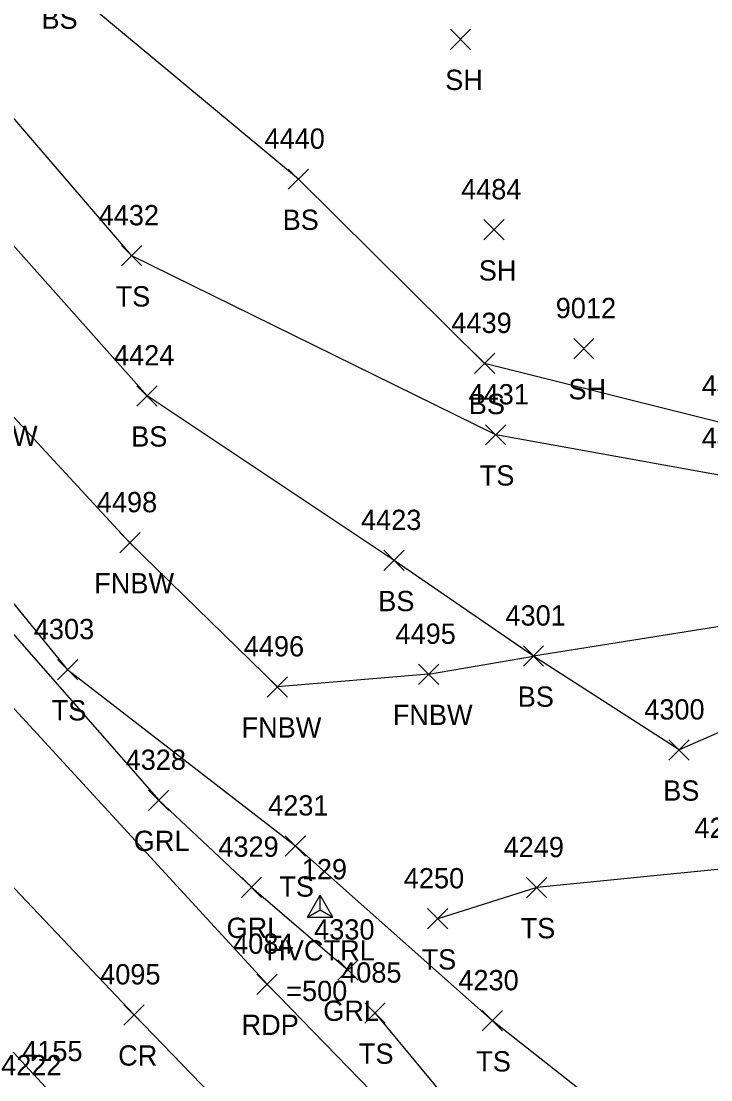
# Model space of a CAD drawing. Extents: x 1482574 to 1485769, y 580696 to 595649.
# Drawn here: x 1483633.6 to 1483701.6, y 583487.9 to 583592.2 of the extents above; entities that cross this region are included whole.
import ezdxf

# ---------------------------------------------------------------- set-up
doc = ezdxf.new("R2010")
doc.units = 0
for name, color, linetype in [('C_A', 7, 'Continuous'), ('C_C', 7, 'Continuous'), ('C_I', 7, 'Continuous'), ('CPSM', 7, 'Continuous'), ('L_A', 7, 'Continuous'), ('L_I', 7, 'Continuous'), ('L_TIC', 7, 'Continuous'), ('LELB', 7, 'Continuous'), ('LFNC', 7, 'Continuous'), ('P_A', 7, 'Continuous'), ('P_I', 7, 'Continuous'), ('P_TIC', 7, 'Continuous'), ('PET', 7, 'Continuous'), ('PRC', 7, 'Continuous'), ('R_A', 7, 'Continuous'), ('R_I', 7, 'Continuous'), ('R_TIC', 7, 'Continuous'), ('RGR', 7, 'Continuous')]:
    doc.layers.add(name, color=color, linetype=linetype)

msp = doc.modelspace()

# ---------------------------------------------------------------- linework, layer by layer
at = {"layer": 'CPSM'}
for p, q in [((1483661.81, 583503.91), (1483663.06, 583506.07)), ((1483664.31, 583503.91), (1483663.06, 583506.07)), ((1483663.06, 583504.63), (1483663.06, 583506.07)), ((1483661.81, 583503.91), (1483663.06, 583504.63)), ((1483663.06, 583504.63), (1483663.06, 583504.63)), ((1483663.06, 583504.63), (1483664.31, 583503.91)), ((1483661.81, 583503.91), (1483664.31, 583503.91))]:
    msp.add_line(p, q, dxfattribs=at)
at = {"layer": 'L_TIC'}
for points in [[(1483675.91, 583589.43), (1483677.91, 583591.43)], [(1483677.91, 583589.43), (1483675.91, 583591.43)], [(1483659.93, 583575.64), (1483661.93, 583577.64)], [(1483661.93, 583575.64), (1483659.93, 583577.64)], [(1483679.22, 583570.65), (1483681.22, 583572.65)], [(1483681.22, 583570.65), (1483679.22, 583572.65)], [(1483643.49, 583568.1), (1483645.49, 583570.09)], [(1483645.49, 583568.1), (1483643.49, 583570.09)], [(1483688.07, 583558.94), (1483690.07, 583560.94)], [(1483690.07, 583558.94), (1483688.07, 583560.94)], [(1483678.28, 583557.48), (1483680.28, 583559.48)], [(1483680.28, 583557.48), (1483678.28, 583559.48)], [(1483645, 583554.28), (1483647, 583556.28)], [(1483647, 583554.28), (1483645, 583556.28)], [(1483679.39, 583550.44), (1483681.39, 583552.44)], [(1483681.39, 583550.44), (1483679.39, 583552.44)], [(1483643.31, 583539.81), (1483645.31, 583541.8)], [(1483645.31, 583539.81), (1483643.31, 583541.8)], [(1483669.36, 583538.06), (1483671.36, 583540.06)], [(1483671.36, 583538.06), (1483669.36, 583540.06)], [(1483683.11, 583528.64), (1483685.11, 583530.64)], [(1483685.11, 583528.64), (1483683.11, 583530.64)], [(1483637.18, 583527.3), (1483639.18, 583529.29)], [(1483639.18, 583527.3), (1483637.18, 583529.29)], [(1483672.76, 583526.84), (1483674.76, 583528.84)], [(1483674.76, 583526.84), (1483672.76, 583528.84)], [(1483657.85, 583525.6), (1483659.85, 583527.6)], [(1483659.85, 583525.6), (1483657.85, 583527.6)], [(1483697.46, 583519.38), (1483699.46, 583521.38)], [(1483699.46, 583519.38), (1483697.46, 583521.38)], [(1483659.63, 583509.92), (1483661.63, 583511.92)], [(1483661.63, 583509.92), (1483659.63, 583511.92)], [(1483683.43, 583505.82), (1483685.43, 583507.82)], [(1483685.43, 583505.82), (1483683.43, 583507.82)], [(1483673.66, 583502.74), (1483675.66, 583504.74)], [(1483675.66, 583502.74), (1483673.66, 583504.74)], [(1483667.48, 583493.45), (1483669.48, 583495.45)], [(1483669.48, 583493.45), (1483667.48, 583495.45)], [(1483679.05, 583492.7), (1483681.05, 583494.69)], [(1483681.05, 583492.7), (1483679.05, 583494.69)]]:
    msp.add_lwpolyline(points, dxfattribs=at)
at = {"layer": 'LELB'}
for points in [[(1483742.4, 583552.69), (1483725.76, 583549.56), (1483703.96, 583552.3), (1483679.28, 583558.48), (1483660.93, 583576.64), (1483637.15, 583596.46), (1483615.07, 583609.81), (1483602.78, 583616.94), (1483607.94, 583643.09), (1483616.8, 583658.52), (1483628.11, 583655.29), (1483633.82, 583672.03), (1483624.29, 583682.77), (1483626.37, 583696.2), (1483621.21, 583717.98), (1483597.21, 583736.66), (1483595.87, 583748.89), (1483596.51, 583775.53), (1483606.42, 583791.46), (1483628.46, 583809.01), (1483643.23, 583813.61)], [(1483638.18, 583528.29), (1483623.83, 583545.9), (1483615.16, 583563.63), (1483598.18, 583580.85), (1483584.91, 583606.41), (1483576.29, 583635.39), (1483571.8, 583664.7), (1483567.86, 583692.01), (1483571.37, 583722.39), (1483575.73, 583749.31), (1483582.05, 583780.14), (1483587.02, 583800.96), (1483586.5, 583812.63)], [(1483741.79, 583540.7), (1483726.53, 583544.33), (1483704.06, 583547.16), (1483680.39, 583551.44), (1483644.49, 583569.09), (1483629.94, 583586.02), (1483612.61, 583602.16), (1483600.95, 583609.44)], [(1483735.81, 583533.58), (1483716.93, 583528.46), (1483698.46, 583520.38), (1483684.11, 583529.64), (1483670.36, 583539.06), (1483646, 583555.28), (1483615.51, 583589.53), (1483606.5, 583601.33)], [(1483638.18, 583528.29), (1483660.63, 583510.92)], [(1483766.23, 583459.85), (1483754.62, 583477), (1483742.54, 583496.59), (1483736.27, 583517.77), (1483716.64, 583511.25), (1483703.24, 583508.71), (1483684.43, 583506.82), (1483674.66, 583503.74)], [(1483809.69, 583356.53), (1483787.72, 583374.89), (1483761.98, 583401.74), (1483738.15, 583426.92), (1483736.24, 583442.93), (1483724.82, 583459.78), (1483706.28, 583473.02), (1483680.05, 583493.69), (1483660.63, 583510.92)], [(1483668.48, 583494.45), (1483691.51, 583466.71), (1483717.71, 583441.81), (1483741.58, 583415.89), (1483765.61, 583390.35), (1483787.36, 583370.39)]]:
    msp.add_lwpolyline(points, dxfattribs=at)
at = {"layer": 'LFNC'}
for points in [[(1483673.76, 583527.84), (1483658.85, 583526.6), (1483644.31, 583540.81), (1483630.87, 583555.33)], [(1483705.13, 583532.97), (1483684.11, 583529.64)], [(1483673.76, 583527.84), (1483684.11, 583529.64)]]:
    msp.add_lwpolyline(points, dxfattribs=at)
at = {"layer": 'P_TIC'}
for points in [[(1483656.83, 583496.29), (1483658.83, 583498.29)], [(1483658.83, 583496.29), (1483656.83, 583498.29)], [(1483643.72, 583493.27), (1483645.72, 583495.27)], [(1483645.72, 583493.27), (1483643.72, 583495.27)]]:
    msp.add_lwpolyline(points, dxfattribs=at)
at = {"layer": 'PET'}
for points in [[(1483734.47, 583384.83), (1483710.77, 583410.08), (1483685.69, 583436.09), (1483659.83, 583462.34), (1483636.38, 583486.71), (1483612.84, 583512.18), (1483585.95, 583538.63), (1483563.03, 583563.69), (1483555.97, 583565.92)], [(1483628.83, 583528.85), (1483657.83, 583497.29)], [(1483757.87, 583394.57), (1483732.77, 583420.47), (1483707.3, 583446.44), (1483681.81, 583472.64), (1483657.83, 583497.29)]]:
    msp.add_lwpolyline(points, dxfattribs=at)
at = {"layer": 'PRC'}
for points in [[(1483618.73, 583521.67), (1483644.72, 583494.27)], [(1484022.3, 583100.04), (1483990.86, 583133.2), (1483962.86, 583162.55), (1483929.32, 583197.8), (1483898.21, 583230.47), (1483864.91, 583265.08), (1483836.8, 583294.4), (1483804.05, 583328.83), (1483747.31, 583388.01), (1483714.35, 583422.23), (1483688.92, 583448.43), (1483665.49, 583472.79), (1483644.72, 583494.27)]]:
    msp.add_lwpolyline(points, dxfattribs=at)
at = {"layer": 'R_TIC'}
for points in [[(1483646.15, 583514.42), (1483648.15, 583516.42)], [(1483648.15, 583514.42), (1483646.15, 583516.42)], [(1483655.3, 583505.85), (1483657.3, 583507.85)], [(1483657.3, 583505.85), (1483655.3, 583507.85)], [(1483664.83, 583497.69), (1483666.83, 583499.68)], [(1483666.83, 583497.69), (1483664.83, 583499.68)]]:
    msp.add_lwpolyline(points, dxfattribs=at)
at = {"layer": 'RGR'}
msp.add_lwpolyline([(1483584.85, 583800.99), (1483581.02, 583785.39), (1483576.51, 583765.04), (1483571.73, 583733.99), (1483567.7, 583702.98), (1483566.07, 583678.04), (1483568.17, 583653.2), (1483573.19, 583628.8), (1483581.79, 583605.84), (1483593.55, 583583.91), (1483607.49, 583563.04), (1483626.65, 583538.8), (1483647.15, 583515.42), (1483656.3, 583506.85), (1483665.83, 583498.69)], dxfattribs=at)

# ---------------------------------------------------------------- texts
at = {"layer": 'C_A'}
msp.add_text('HVCTRL', height=2, dxfattribs=at).set_placement((1483657.76, 583499.63))
at = {"layer": 'C_C'}
msp.add_text('=500', height=2, dxfattribs=at).set_placement((1483659.72, 583495.63))
at = {"layer": 'C_I'}
msp.add_text('129', height=2, dxfattribs=at).set_placement((1483661.26, 583507.63))
at = {"layer": 'L_A'}
for s, p in [('BS', (1483635.59, 583591.46)), ('SH', (1483675.4, 583585.43)), ('BS', (1483659.37, 583571.64)), ('SH', (1483678.71, 583566.65)), ('TS', (1483642.9, 583564.09)), ('SH', (1483687.56, 583554.94)), ('BS', (1483677.72, 583553.48)), ('FNBW', (1483627.34, 583550.33)), ('BS', (1483644.44, 583550.28)), ('TS', (1483678.8, 583546.44)), ('FNBW', (1483640.79, 583535.81)), ('BS', (1483668.8, 583534.06)), ('BS', (1483682.55, 583524.64)), ('TS', (1483636.59, 583523.29)), ('FNBW', (1483670.23, 583522.84)), ('FNBW', (1483655.32, 583521.6)), ('BS', (1483696.9, 583515.38)), ('TS', (1483659.04, 583505.92)), ('TS', (1483682.84, 583501.82)), ('TS', (1483673.07, 583498.74)), ('TS', (1483666.89, 583489.45)), ('TS', (1483678.46, 583488.69))]:
    msp.add_text(s, height=2, dxfattribs=at).set_placement(p)
at = {"layer": 'L_I'}
for s, p in [('4440', (1483657.58, 583579.64)), ('4484', (1483676.97, 583574.65)), ('4432', (1483641.23, 583572.09)), ('9012', (1483686.3, 583562.94)), ('4439', (1483676.01, 583561.48)), ('4424', (1483642.74, 583558.28)), ('4438', (1483700.71, 583555.3)), ('4431', (1483677.7, 583554.44)), ('4430', (1483700.71, 583550.16)), ('4498', (1483641.05, 583543.81)), ('4423', (1483667.1, 583542.06)), ('4301', (1483681.34, 583532.64)), ('4303', (1483634.84, 583531.3)), ('4495', (1483670.5, 583530.84)), ('4496', (1483655.54, 583529.6)), ('4300', (1483695.03, 583523.38)), ('4231', (1483657.94, 583513.92)), ('4248', (1483699.98, 583511.71)), ('4249', (1483681.16, 583509.82)), ('4250', (1483671.32, 583506.74)), ('4085', (1483665.14, 583497.45)), ('4230', (1483676.7, 583496.69)), ('4222', (1483631.62, 583488.31))]:
    msp.add_text(s, height=2, dxfattribs=at).set_placement(p)
at = {"layer": 'P_A'}
for s, p in [('RDP', (1483655.32, 583492.29)), ('CR', (1483643.15, 583489.27))]:
    msp.add_text(s, height=2, dxfattribs=at).set_placement(p)
at = {"layer": 'P_I'}
for s, p in [('4084', (1483654.49, 583500.29)), ('4095', (1483641.38, 583497.27)), ('4155', (1483633.69, 583489.71))]:
    msp.add_text(s, height=2, dxfattribs=at).set_placement(p)
at = {"layer": 'R_A'}
for p in [(1483644.69, 583510.42), (1483653.84, 583501.85), (1483663.37, 583493.68)]:
    msp.add_text('GRL', height=2, dxfattribs=at).set_placement(p)
at = {"layer": 'R_I'}
for s, p in [('4328', (1483643.89, 583518.42)), ('4329', (1483653.03, 583509.85)), ('4330', (1483662.48, 583501.69))]:
    msp.add_text(s, height=2, dxfattribs=at).set_placement(p)

doc.saveas('drawing.dxf')
